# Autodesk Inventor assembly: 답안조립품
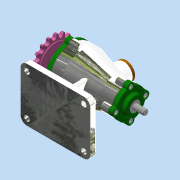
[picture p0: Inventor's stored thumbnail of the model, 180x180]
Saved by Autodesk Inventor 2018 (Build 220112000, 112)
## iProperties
Created: 2020-12
Part Number: 답안조립품
Material: 일반
Document SubType Name: Assembly
Designer: home
Author: home
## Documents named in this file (15)
- C:\Users\home\Desktop\701206V1025\답안조립품.iam
- C:\Users\home\Desktop\701206V1025\본체.ipt
- C:\Users\home\Desktop\701206V1025\축.ipt
- C:\Users\home\Desktop\701206V1025\뒤커버.ipt
- C:\Users\home\Desktop\701206V1025\베어링 6200.ipt
- C:\Users\home\Desktop\701206V1025\오일 실 10 20 7.ipt
- C:\Users\home\Desktop\701206V1025\베어링 6203.ipt
- C:\Users\home\Desktop\701206V1025\개스킷 B.ipt
- C:\Users\home\Desktop\701206V1025\개스킷 A.ipt
- C:\Users\home\Desktop\701206V1025\앞커버.ipt
- C:\Users\home\Desktop\701206V1025\오일 실 17 30 8.ipt
- C:\Users\home\Desktop\701206V1025\키 4x4x14.ipt
- C:\Users\home\Desktop\701206V1025\스프로킷.ipt
- C:\Users\home\Desktop\701206V1025\마개.ipt
- C:\Users\home\Desktop\701206V1025\볼트 M5.ipt
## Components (2 placed, 2 different names)
1. 개스킷 B:1
2. 개스킷 A:1
